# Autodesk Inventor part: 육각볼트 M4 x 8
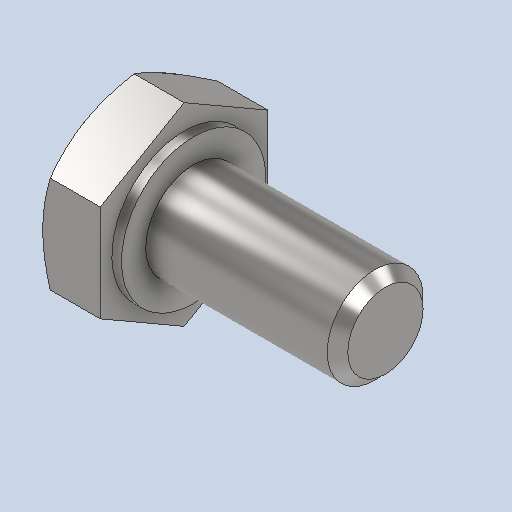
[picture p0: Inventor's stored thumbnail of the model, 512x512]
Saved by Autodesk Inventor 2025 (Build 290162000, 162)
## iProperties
Created: 2024-07
Part Number: 육각볼트 M4 x 8
Material: 강철, 연강
Description: 6각 머리 나사
Document SubType Name: Modeling
Designer: SAMSUNG
Density: 7.86 g/cm^3
Appearance: 기본값
Author: jhkim
Sending System: Autodesk Inventor 2025
Preprocessor: ST-DEVELOPER v20
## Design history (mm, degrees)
feature "Solid1"
node "솔리드1"
